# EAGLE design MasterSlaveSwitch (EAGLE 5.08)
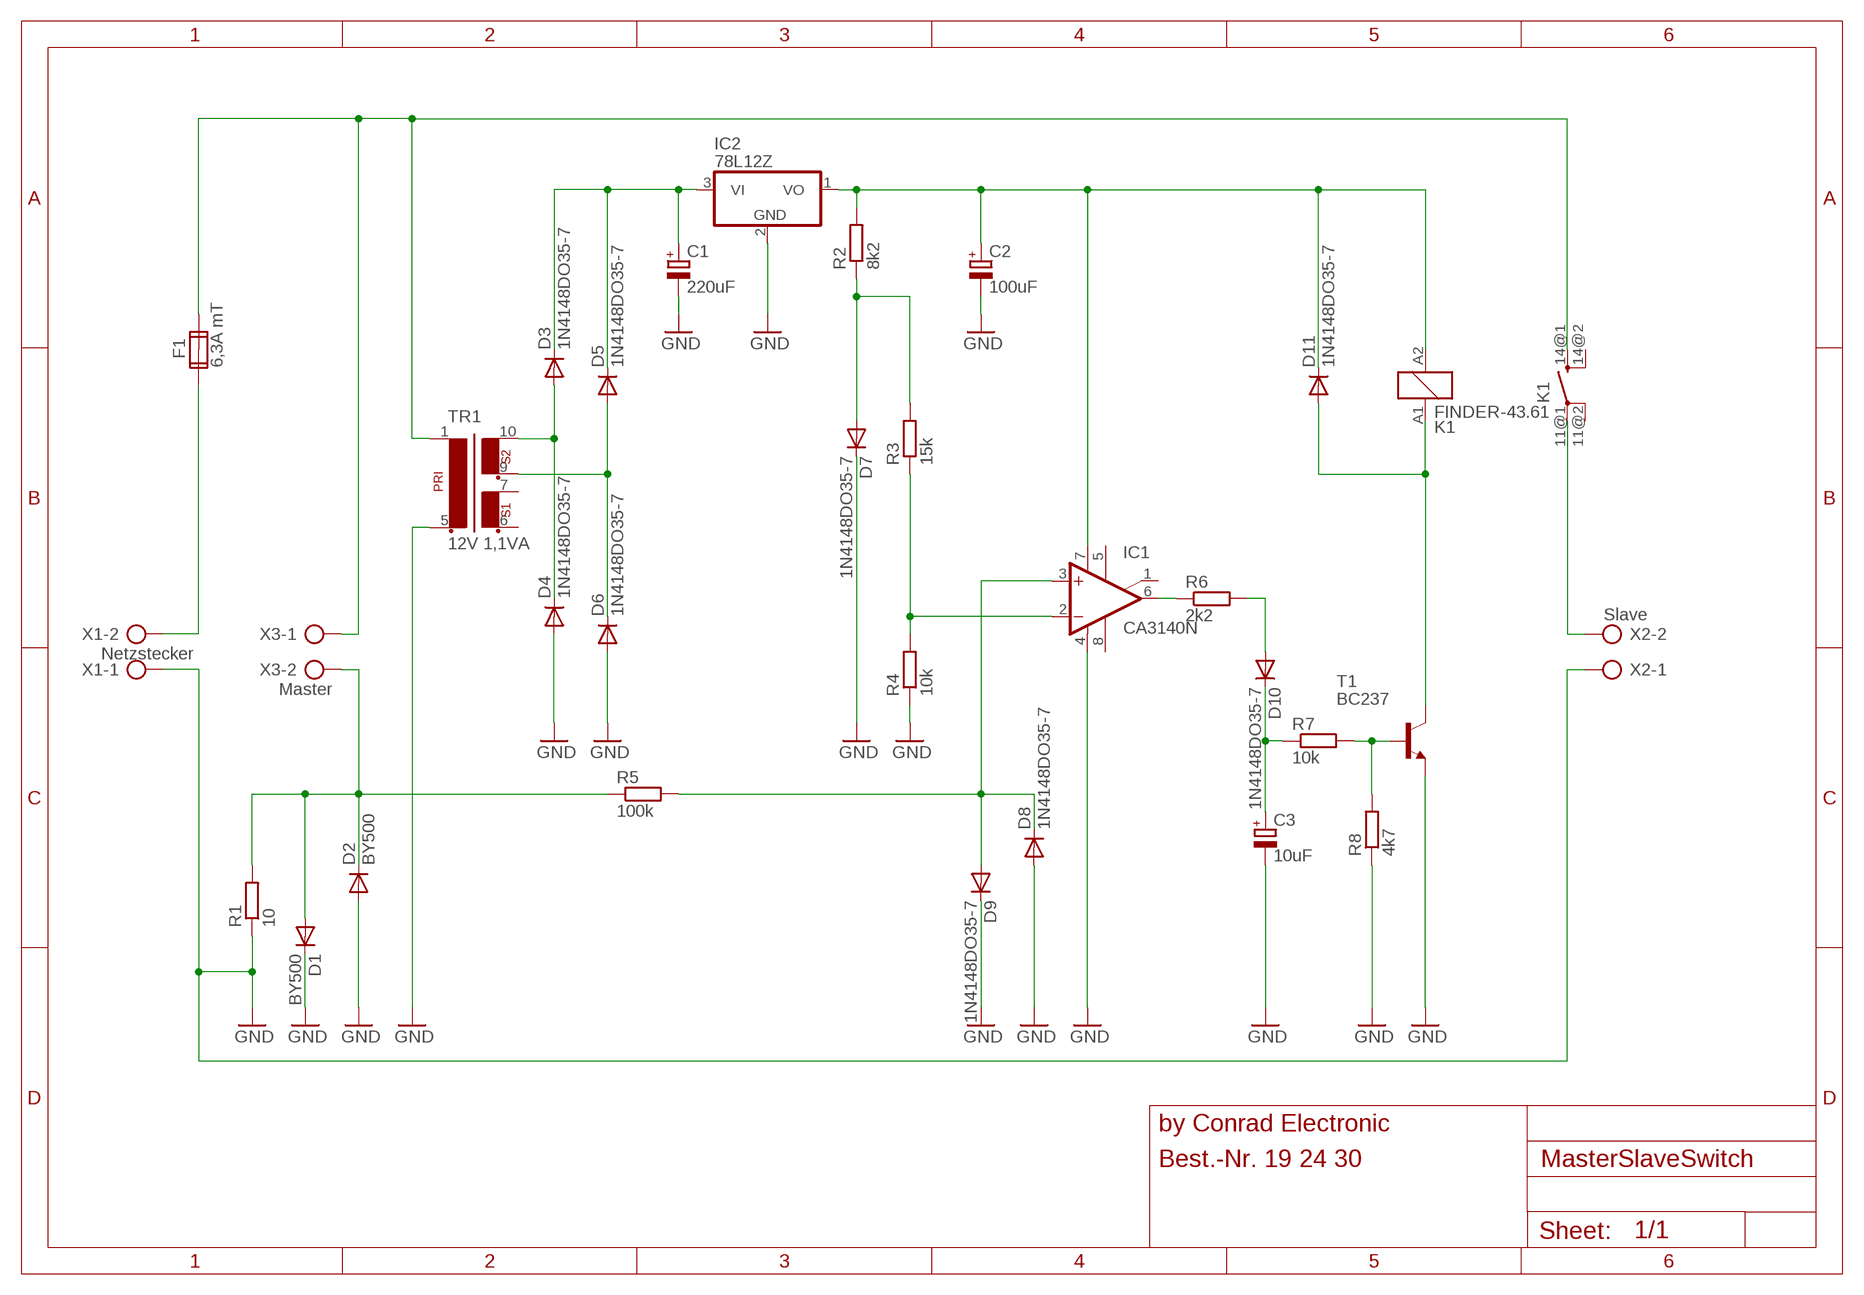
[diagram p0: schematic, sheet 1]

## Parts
C1  220uF  CPOL-EUE2-5  [E2-5]
C2  100uF  CPOL-EUE2-5  [E2-5]
C3  10uF  CPOL-EUE2-5  [E2-5]
D1  BY500  [DO201-15]
D2  BY500  [DO201-15]
D3  1N4148DO35-7  [DO35-7]
D4  1N4148DO35-7  [DO35-7]
D5  1N4148DO35-7  [DO35-7]
D6  1N4148DO35-7  [DO35-7]
D7  1N4148DO35-7  [DO35-7]
D8  1N4148DO35-7  [DO35-7]
D9  1N4148DO35-7  [DO35-7]
D10  1N4148DO35-7  [DO35-7]
D11  1N4148DO35-7  [DO35-7]
F1  6,3A mT  FUSE2P  [FUSE1]
IC1  CA3140N  [DIL08]
IC2  78L12Z  [TO92]
K1  FINDER-43.61  [FINDER-43.61]
R1  10  R-EU_0207/10  [0207/10]
R2  8k2  R-EU_0207/10  [0207/10]
R3  15k  R-EU_0207/10  [0207/10]
R4  10k  R-EU_0207/10  [0207/10]
R5  100k  R-EU_0207/10  [0207/10]
R6  2k2  R-EU_0207/10  [0207/10]
R7  10k  R-EU_0207/10  [0207/10]
R8  4k7  R-EU_0207/10  [0207/10]
T1  BC237  [TO92]
TR1  12V 1,1VA  EI30-2  [EI30-2]
X1  Netzstecker  AK300/2  [AK300/2]
X2  Slave  AK300/2  [AK300/2]
X3  Master  AK300/2  [AK300/2]

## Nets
GND: C1.- C2.- C3.- D1.C D2.A D4.A D6.A D7.C D8.A D9.C IC1.4(V-) IC2.2(GND) R1.1 R4.1 R8.1 T1.1(E) TR1.5 X1.1 X2.1
N$1: D1.A D2.C R1.2 R5.1 X3.2
N$2: D3.A D4.C TR1.10
N$3: F1.1A X1.2
N$4: F1.2A K1.14@1(-1:SA) TR1.1 X3.1
N$5: D5.A D6.C TR1.9
N$6: K1.11@1(-1:PA) X2.2
N$7: C1.+ D3.C D5.C IC2.3(VI)
N$8: C2.+ D11.C IC1.7(V+) IC2.1(VO) K1.A2 R2.2
N$9: D7.A R2.1 R3.2
N$11: IC1.2(-IN) R3.1 R4.2
N$13: D8.C D9.A IC1.3(+IN) R5.2
N$14: IC1.6(OUT) R6.1
N$15: D10.A R6.2
N$16: C3.+ D10.C R7.1
N$17: R7.2 R8.2 T1.2(B)
N$18: D11.A K1.A1 T1.3(C)
Unconnected: F1.1B F1.2B IC1.1(ON/CMP) IC1.5(ON) IC1.8(CMP) K1.11@2(-1:PB) K1.14@2(-1:SB) TR1.6 TR1.7

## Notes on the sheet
- by Conrad Electronic
- Best.-Nr. 19 24 30

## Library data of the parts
C1-C3 = resistor:CPOL-EU: POLARIZED CAPACITOR, European symbol
D1 D2 = diode:BY500: DIODE
D3-D11 = diode:1N4148: DIODE
F1 = special:FUSE2P: FUSE 5 x 20 mm
IC1 = linear:CA3140: OP AMP
IC2 = linear:78*: Positive VOLTAGE REGULATOR Source: http://cache.national.com/ds/LM/LM78L05.pdf http://www.fairchildsemi.com/ds/LM/LM7805.pdf
K1 = relay:FINDER-43.61: Low profile PCB relays 10 - 16 A FINDER 43 Series Kontakt max. AC- 250V, Strom - Kontakt AC- max. 10A 5 mm contact pin pitch, 1 Pole NO, 16 A, PCB mount Distributor: FARNELL Source: http://www.farnell.com/datasheets/87682.pdf
R1-R8 = resistor:R-EU_: RESISTOR, European symbol
T1 = transistor:BC237: NPN TRANSISTOR
TR1 = trafo:EI30-2: TRANSFORMER 1 primary winding, 2 secondary windings ERA
X1-X3 = con-ptr500:AK300/2: CONNECTOR

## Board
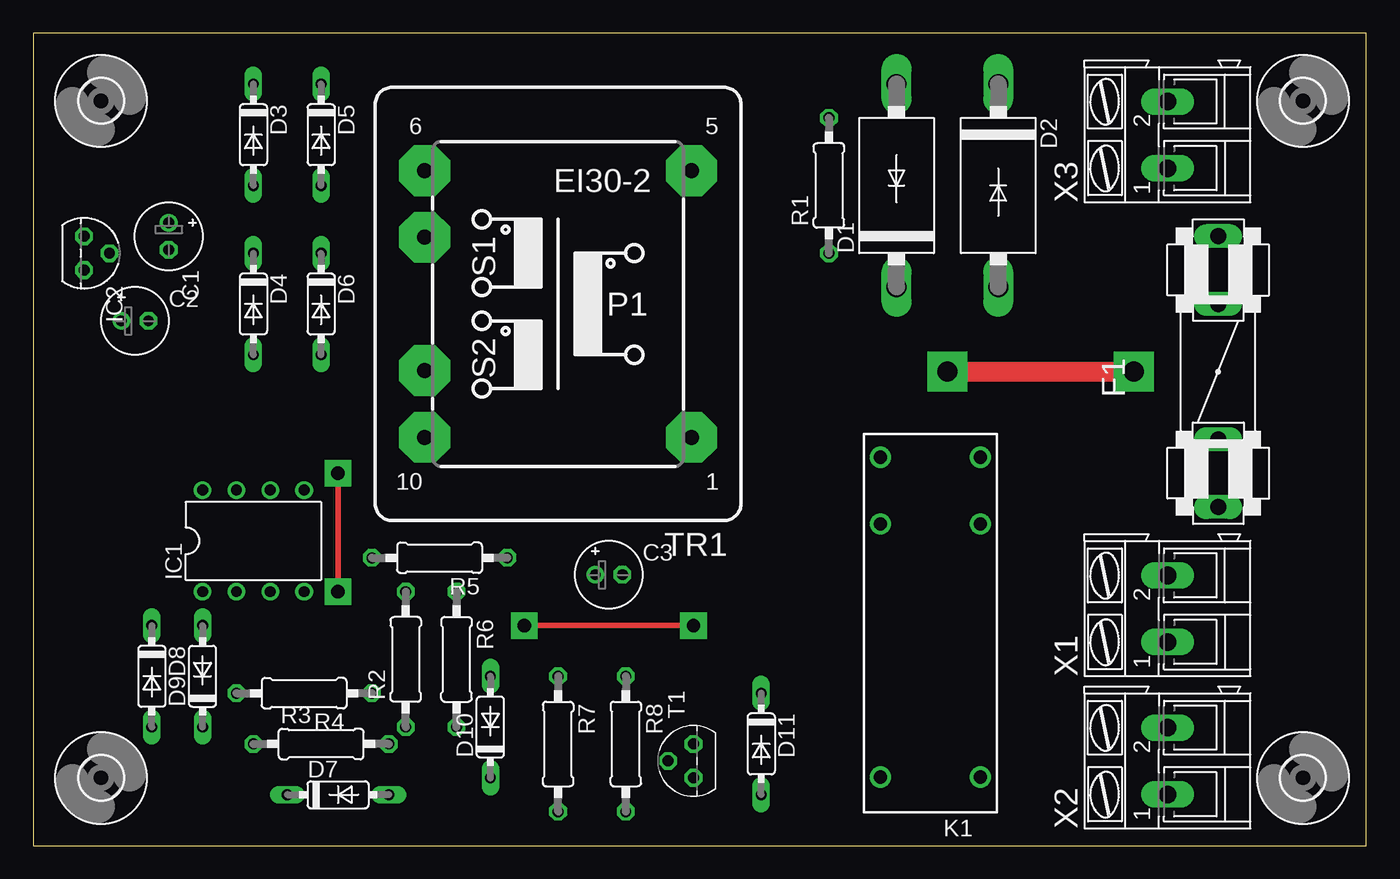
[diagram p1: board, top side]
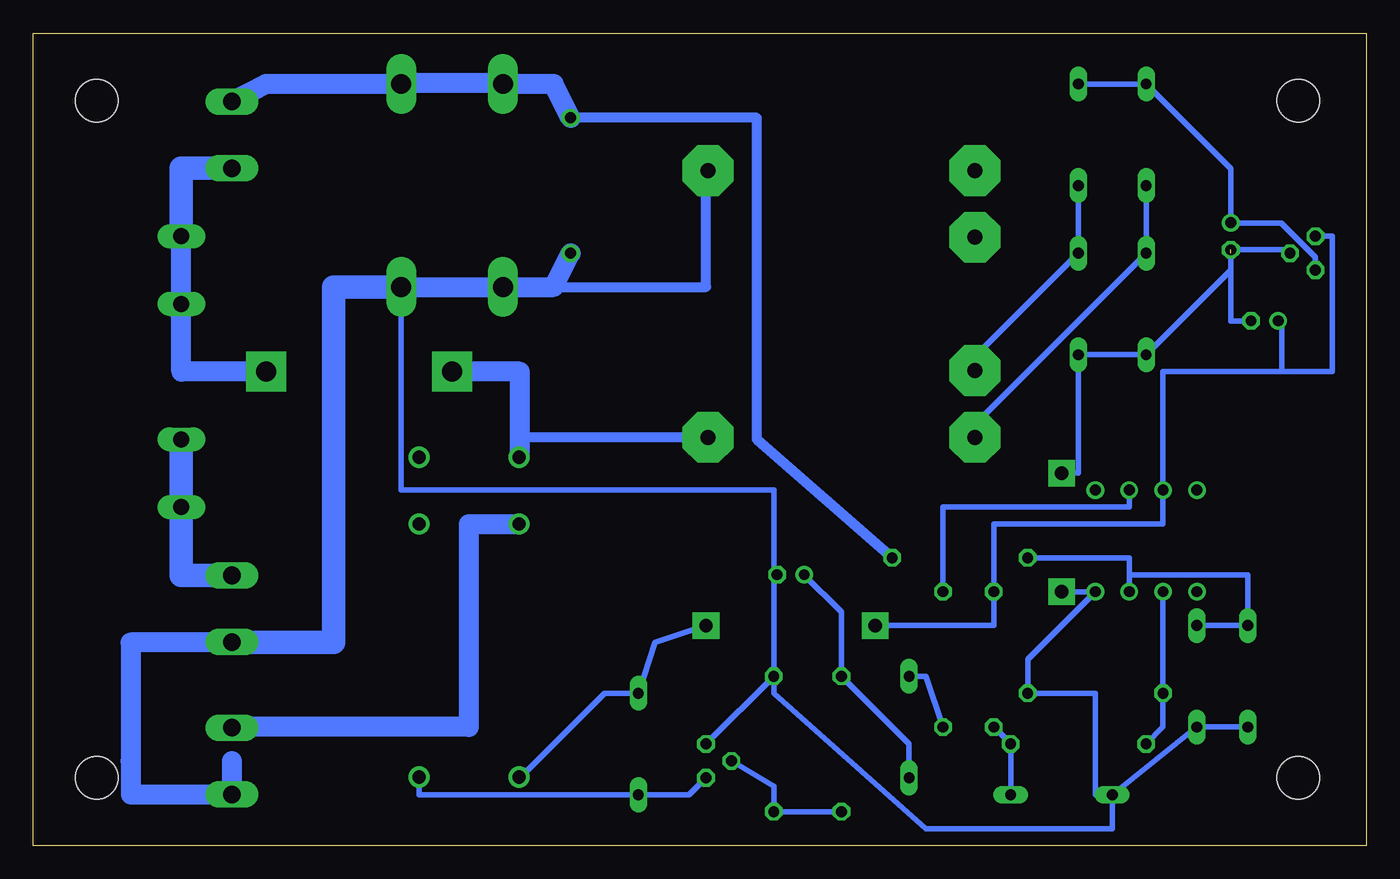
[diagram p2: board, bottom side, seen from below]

Size 100 x 60.95 mm. Coordinates in mm from the lower left corner, seen from the top.
Outline: 0,0 100,0 100,60.95 0,60.95 0,0
Copper layers (1*16): Top 0.035mm / dielectric 1.5mm / Bottom 0.035mm
Design rules "default": minimum track width 10mil, minimum drill 24mil, track to track 8mil, track to pad 8mil, pad to pad 8mil, via to via 8mil, smd to smd 8mil, copper to edge 40mil, drill to drill 8mil, minimum pad ring 10mil, minimum via ring 8mil, stop-mask expansion 4mil, vias tented up to drill 0mil, thermal gap 10mil

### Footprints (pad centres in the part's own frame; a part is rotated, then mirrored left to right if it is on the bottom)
E2-5 = drill 0.813 pad 1.27 round: + -1.016,0 | drill 0.813 pad 1.27 octagon: - 1.016,0
DO201-15 = drill 1.499 long: A 7.62,0; C -7.62,0
DO35-7 = drill 0.813 long: A 3.81,0; C -3.81,0
FUSE1 = drill 1.194 long: 1A -10.16,0; 1B -5.08,0; 2A 10.16,0; 2B 5.08,0
DIL08 = drill 0.813 pad 1.27 round: 1 -3.81,-3.81; 2 -1.27,-3.81; 3 1.27,-3.81; 4 3.81,-3.81; 5 3.81,3.81; 6 1.27,3.81; 7 -1.27,3.81; 8 -3.81,3.81
TO92 = drill 0.813 octagon: 1 -1.27,0; 2 0,1.905; 3 1.27,0
FINDER-43.61 = drill 1 pad 1.6 round: 11@1 0,3.75; 11@2 0,-3.75; 14@1 5,3.75; 14@2 5,-3.75; A1 -19,-3.75; A2 -19,3.75
0207/10 = drill 0.813 octagon: 1 -5.08,0; 2 5.08,0
TO92' = drill 0.813 octagon: 1 1.27,0; 2 0,1.905; 3 -1.27,0
EI30-2 = drill 1.118 pad 3.81 octagon: 1 -10.008,10.008; 5 -10.008,-10.008; 6 10.008,-10.008; 7 10.008,-5.004; 9 10.008,5.004; 10 10.008,10.008
3,2 = hole 3.2: 0,0
AK300/2 = drill 1.321 long: 1 -2.515,0; 2 2.489,0

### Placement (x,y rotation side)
C1  10.16,45.72 270 top
C2  7.62,39.37 0 top
C3  43.18,20.32 0 top
D1  64.77,49.53 90 top
D2  72.39,49.53 270 top
D3  16.51,53.34 270 top
D4  16.51,40.64 270 top
D5  21.59,53.34 270 top
D6  21.59,40.64 270 top
D7  22.86,3.81 0 top
D8  8.89,12.7 270 top
D9  12.7,12.7 90 top
D10  34.29,8.89 90 top
D11  54.61,7.62 270 top
F1  88.9,35.56 90 top
IC1  16.51,22.86 0 top
IC2  3.81,44.45 270 top
K1  67.31,24.13 90 top
R1  59.69,49.53 90 top
R2  27.94,13.97 90 top
R3  21.59,7.62 0 top
R4  20.32,11.43 180 top
R5  30.48,21.59 180 top
R6  31.75,13.97 270 top
R7  39.37,7.62 270 top
R8  44.45,7.62 270 top
T1  BC237  [TO92']  49.53,6.35 90 top
TR1  39.37,40.64 180 top
U$1  [3,2]  5.08,55.88 0 top
U$2  [3,2]  95.25,55.88 0 top
U$3  [3,2]  95.25,5.08 0 top
U$4  [3,2]  5.08,5.08 0 top
X1  85.09,17.78 90 top
X2  85.09,6.35 90 top
X3  85.09,53.34 90 top

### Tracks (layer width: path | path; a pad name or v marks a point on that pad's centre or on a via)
GND  (via drill 1 pad 2)  (2 unrouted)
  Top 0.406: v22.86,19.05 v22.86,27.94
  Bottom 0.406: R8.1 44.45,20.07 | D2.A 72.39,26.67 44.45,26.67 44.45,20.07 | R8.1 T1.1 | 44.45,20.07 C3.- | 10.16,43.18 C1.- 5.97,44.7 IC2.2 | 10.16,43.18 D4.A D6.A 21.59,27.94 v22.86,27.94 | D8.A D9.C D7.C | D7.C 20.32,3.81 20.32,11.43 R4.1 25.4,13.97 IC1.4 v22.86,19.05 | R8.1 44.45,11.43 33.02,1.27 19.05,1.27 D7.C | C2.- 10.16,39.37 10.16,43.18
  Bottom 0.75: 49.53,50.49 49.53,41.91 D1.C
  Bottom 1.5: 85.09,6.35 X2.1 92.69,3.83 92.71,6.35 92.71,15.24 85.11,15.24 X1.1 | R1.1 60.96,41.91 D1.C D2.A | 49.53,50.49 TR1.5
  Bottom 1.75: D2.A 77.47,41.91 77.47,15.24 85.09,15.24 X1.1
N$1
  Bottom 0.75: R1.2 45.72,54.61 45.72,30.48 R5.1
  Bottom 1.5: R1.2 60.96,57.15 D1.A 64.82,57.2 72.34,57.2 D2.C 82.55,57.15 X3.2
N$2
  Bottom 0.406: TR1.10 29.36,31.6 D4.C D3.A
N$3
  Bottom 1.75: X1.2 88.9,20.27 F1.1A 88.9,30.48
N$4  (via drill 1.5 pad 3)
  Top 1.5: v68.58,35.56 v82.55,35.56
  Bottom 0.75: TR1.1 63.56,30.63 K1.14@1
  Bottom 1.5: v82.55,35.56 88.9,35.56 F1.2A | K1.14@1 63.5,29.13 63.5,35.56 v68.58,35.56
  Bottom 1.75: X3.1 88.9,50.83 F1.2A
N$5
  Bottom 0.406: TR1.9 29.36,36.68 D6.C D5.A
N$6
  Bottom 1.5: K1.11@1 67.31,24.13 67.31,8.89 85.09,8.89 X2.2
N$7
  Bottom 0.406: D5.C D3.C 10.16,50.8 C1.+ 10.13,46.71 6.37,46.71 3.81,44.15 IC2.3
N$8  (via drill 1 pad 2)
  Top 0.406: v36.83,16.51 v49.53,16.51
  Bottom 0.406: K1.A2 63.5,5.13 63.5,5.08 57.15,11.43 D11.C 53.34,15.24 v49.53,16.51 | IC2.1 2.54,45.72 2.54,35.56 6.35,35.56 | 6.35,35.56 15.24,35.56 IC1.7 15.24,24.13 27.94,24.13 R2.2 27.94,16.51 v36.83,16.51 | C2.+ 6.35,39.37 6.35,35.56
N$9
  Bottom 0.406: R2.1 R3.2 D7.A
N$11
  Bottom 0.406: IC1.2 R4.2 15.24,8.89 R3.1
N$13
  Bottom 0.406: D9.A D8.C 8.89,20.32 17.78,20.32 IC1.3 17.78,21.59 R5.2
N$14
  Bottom 0.406: IC1.6 17.78,25.4 31.75,25.4 R6.1
N$15
  Bottom 0.406: D10.A 33.02,12.7 R6.2
N$16
  Bottom 0.406: D10.C 34.29,7.62 R7.1 39.37,17.53 C3.+
N$17
  Bottom 0.406: T1.2 44.45,4.45 R8.2 R7.2
N$18
  Bottom 0.406: K1.A1 71.06,3.81 D11.A 50.8,3.81 T1.3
